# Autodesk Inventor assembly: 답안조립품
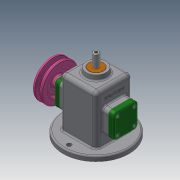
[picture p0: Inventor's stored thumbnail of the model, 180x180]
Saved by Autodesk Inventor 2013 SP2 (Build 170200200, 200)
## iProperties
Created: 2021-08
Part Number: 답안조립품
Document SubType Name: Assembly
Designer: kumco
Author: kumco
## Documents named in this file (16)
- C:\Users\kumco\Desktop\710806V1020\답안조립품.iam
- C:\Users\kumco\Desktop\710806V1020\본체.ipt
- C:\Users\kumco\Desktop\710806V1020\V벨트풀리.ipt
- C:\Users\kumco\Desktop\710806V1020\고정핀 1.2x8.ipt
- C:\Users\kumco\Desktop\710806V1020\뒤커버.ipt
- C:\Users\kumco\Desktop\710806V1020\링크.ipt
- C:\Users\kumco\Desktop\710806V1020\멈춤나사 M3x8.ipt
- C:\Users\kumco\Desktop\710806V1020\베어링 12x32x10.ipt
- C:\Users\kumco\Desktop\710806V1020\볼트 M4.ipt
- C:\Users\kumco\Desktop\710806V1020\부시.ipt
- C:\Users\kumco\Desktop\710806V1020\슬라이드.ipt
- C:\Users\kumco\Desktop\710806V1020\앞커버.ipt
- C:\Users\kumco\Desktop\710806V1020\오일 실 12 25 7.ipt
- C:\Users\kumco\Desktop\710806V1020\키 4x4x10.ipt
- C:\Users\kumco\Desktop\710806V1020\편심축.ipt
- C:\Users\kumco\Desktop\710806V1020\핀 5x18.ipt
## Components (3 placed, 3 different names)
1. V벨트풀리:1
2. 고정핀 1.2x8:1
3. 핀 5x18:1
